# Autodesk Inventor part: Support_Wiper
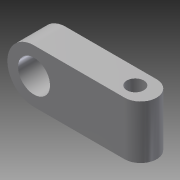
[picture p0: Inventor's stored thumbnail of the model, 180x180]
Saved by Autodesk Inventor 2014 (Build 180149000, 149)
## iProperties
Created: 2006-03
Part Number: Support_Wiper
Document SubType Name: Modeling
Designer: debonom
Material: Stainless Steel, 440C
Mass: 138.885 g
Surface Area: 61.269 cm^2
Volume: 17.9206 cm^3
Density: 7.75 g/cm^3
Appearance: Steel
Author: debonom
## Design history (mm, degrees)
sketch "Sketch1"
  geometry: L1 (-37.5, 0)-(50, 0) reference; L2 (25, 12.5)-(-25, 12.5); L3 (-25, 12.5)-(-25, -12.5); L4 (-25, -12.5)-(25, -12.5); L5 (25, -12.5)-(25, 12.5); L6 (25, 12.5)-(-25, -12.5); A1 r 12.5 centre (25, 0) between (25, -12.5) and (25, 12.5); 1 further point
  constraints: 10 end point, 2 midpoint, 2 parallel, 2 point on circle, 1 centre point, 1 horizontal, 1 perpendicular, 1 point on line
  dimensions: "d11" = 25 distance of L4.end L2.start; "d12" = 50 distance of L2.start L2.end
extrude "Extrusion1" new body sketch "Sketch1" stored distance "d3" = 15; taper "d4" = 0 deg
sketch "Sketch4"
  geometry: C1 r 7.5 at (25, 0); A1 r 12.5 centre (25, 0) between (25, -12.5) and (25, 12.5) reference; 1 further point
  constraints: 1 centre point, 1 coincident
  dimensions: "d13" = 15 diameter of C1
extrude "Extrusion3" cut sketch "Sketch4" stored distance "d14" = 15; taper "d15" = 0 deg
sketch "Sketch3"
  geometry: L1 (-5, 0)-(30, 0) reference; L2 (25, -7.5)-(25, 7.5) reference; C1 r 4 at (15, 0); 1 further point
  constraints: 1 centre point, 1 point on line
  dimensions: "d8" = 8 diameter of C1; "d16" = 10 distance from line of L2 C1.centre
extrude "Extrusion2" cut sketch "Sketch3" stored distance "d9" = 15; taper "d10" = 0 deg
fillet "Fillet2"
body "Solid1"
